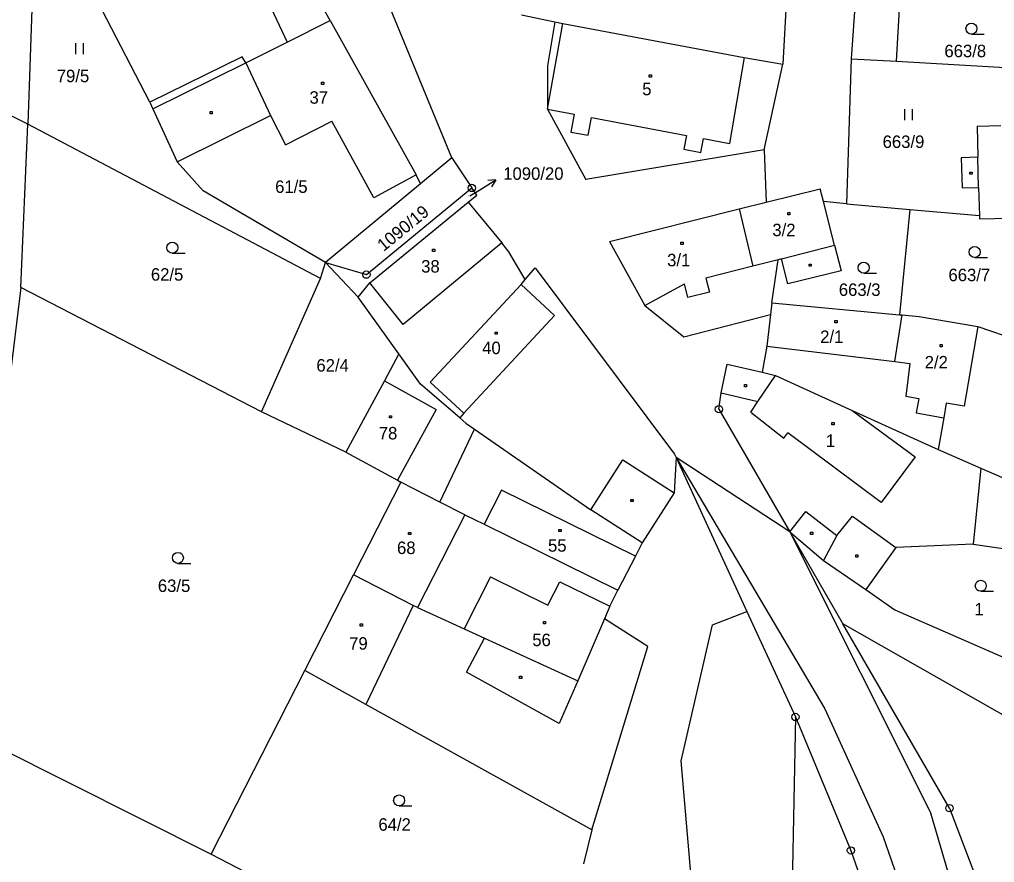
# Model space of a CAD drawing. Extents: x -794142 to -791199, y -1109267 to -1105626.
# Drawn here: x -793459.6 to -793326.7, y -1108046.6 to -1107931.8 of the extents above; entities that cross this region are included whole.
import ezdxf

# ---------------------------------------------------------------- set-up
doc = ezdxf.new("R2010")
doc.units = 0
for name, color, linetype in [('Komunikace', 7, 'Continuous'), ('Vrstva 1', 7, 'Continuous'), ('Vrstva 14', 7, 'Continuous'), ('Vrstva 15', 7, 'Continuous'), ('Vrstva 16', 7, 'Continuous'), ('Vrstva 2', 7, 'Continuous'), ('Vrstva 23', 7, 'Continuous'), ('Vrstva 25', 7, 'Continuous'), ('Vrstva 28', 7, 'Continuous')]:
    doc.layers.add(name, color=color, linetype=linetype)

msp = doc.modelspace()

# ---------------------------------------------------------------- linework, layer by layer
at = {"layer": 'Komunikace'}
msp.add_line((-793398.22, -1107955.82), (-793397.22, -1107955.2), dxfattribs=at)
at = {"layer": 'Vrstva 1'}
for p, q in [((-793354.79, -1107924.2), (-793355.57, -1107937.84)), ((-793345.34, -1107923.91), (-793346.26, -1107937.12)), ((-793400.69, -1107950.63), (-793411.16, -1107925.15)), ((-793425.68, -1107929.45), (-793423.1, -1107934.86)), ((-793417.25, -1107931.93), (-793418.43, -1107929.8)), ((-793457.93, -1107930.38), (-793458.47, -1107946.04)), ((-793441.86, -1107943.04), (-793448.32, -1107930.51)), ((-793391.17, -1107931.15), (-793386.63, -1107932.07)), ((-793340.09, -1107937.44), (-793339.66, -1107930.3)), ((-793423.1, -1107934.86), (-793417.25, -1107931.93)), ((-793386.63, -1107932.07), (-793387.62, -1107938.08)), ((-793386.63, -1107932.07), (-793385.56, -1107932.3)), ((-793385.56, -1107932.3), (-793360.83, -1107936.95)), ((-793428.76, -1107937.7), (-793423.1, -1107934.86)), ((-793429.25, -1107936.86), (-793441.86, -1107943.04)), ((-793428.76, -1107937.7), (-793429.25, -1107936.86)), ((-793387.62, -1107938.08), (-793387.63, -1107944.01)), ((-793360.83, -1107936.95), (-793355.57, -1107937.84)), ((-793358.12, -1107949.53), (-793355.57, -1107937.84)), ((-793346.26, -1107937.12), (-793346.9, -1107956.91)), ((-793346.26, -1107937.12), (-793340.09, -1107937.44)), ((-793340.09, -1107937.44), (-793319.65, -1107938.63)), ((-793441.86, -1107943.04), (-793441.44, -1107943.95)), ((-793458.47, -1107946.04), (-793462.94, -1107943.85)), ((-793441.44, -1107943.95), (-793438.11, -1107951.18)), ((-793387.63, -1107944.01), (-793382.42, -1107953.57)), ((-793459.42, -1107968.29), (-793458.47, -1107946.04)), ((-793418.59, -1107967.07), (-793458.47, -1107946.04)), ((-793438.11, -1107951.18), (-793425.38, -1107944.85)), ((-793425.38, -1107944.85), (-793423.36, -1107948.85)), ((-793423.36, -1107948.85), (-793417.03, -1107945.64)), ((-793411.32, -1107956.08), (-793417.03, -1107945.64)), ((-793329.08, -1107946.32), (-793325.86, -1107946.24)), ((-793329.08, -1107946.32), (-793328.97, -1107950.55)), ((-793358.12, -1107949.53), (-793382.42, -1107953.57)), ((-793358.12, -1107949.53), (-793357.84, -1107956.68)), ((-793434.57, -1107955.12), (-793438.11, -1107951.18)), ((-793400.69, -1107950.63), (-793404.94, -1107954.16)), ((-793400.69, -1107950.63), (-793397.96, -1107954.73)), ((-793328.97, -1107950.55), (-793331.25, -1107950.61)), ((-793331.25, -1107950.61), (-793331.14, -1107954.71)), ((-793405.56, -1107952.95), (-793411.32, -1107956.08)), ((-793404.94, -1107954.16), (-793405.56, -1107952.95)), ((-793417.88, -1107964.9), (-793434.57, -1107955.12)), ((-793404.94, -1107954.16), (-793417.88, -1107964.9)), ((-793412.32, -1107966.54), (-793397.96, -1107954.73)), ((-793397.26, -1107955.72), (-793397.96, -1107954.73)), ((-793357.84, -1107956.68), (-793350.49, -1107954.84)), ((-793350.04, -1107956.58), (-793350.49, -1107954.84)), ((-793331.14, -1107954.71), (-793328.87, -1107954.65)), ((-793328.87, -1107954.65), (-793328.77, -1107958.48)), ((-793411.84, -1107967.64), (-793398.46, -1107956.67)), ((-793398.46, -1107956.67), (-793397.26, -1107955.72)), ((-793398.46, -1107956.67), (-793393.84, -1107962.21)), ((-793361.5, -1107957.59), (-793357.84, -1107956.68)), ((-793348.52, -1107962.52), (-793350.04, -1107956.58)), ((-793346.9, -1107956.91), (-793350.04, -1107956.58)), ((-793379.19, -1107962.01), (-793361.5, -1107957.59)), ((-793361.5, -1107957.59), (-793359.65, -1107965.38)), ((-793346.9, -1107956.91), (-793338.24, -1107957.66)), ((-793338.24, -1107957.66), (-793339.66, -1107972)), ((-793338.24, -1107957.66), (-793328.77, -1107958.48)), ((-793328.77, -1107958.48), (-793328.76, -1107958.95)), ((-793328.76, -1107958.95), (-793324.56, -1107958.84)), ((-793379.19, -1107962.01), (-793374.36, -1107970.74)), ((-793392.89, -1107963.44), (-793393.84, -1107962.21)), ((-793348.52, -1107962.52), (-793347.61, -1107966.04)), ((-793390.68, -1107967.22), (-793392.89, -1107963.44)), ((-793356.22, -1107964.5), (-793359.65, -1107965.38)), ((-793357.08, -1107970.39), (-793356.22, -1107964.5)), ((-793355.76, -1107964.38), (-793356.22, -1107964.5)), ((-793354.89, -1107967.79), (-793355.76, -1107964.38)), ((-793418.59, -1107967.07), (-793417.88, -1107964.9)), ((-793417.88, -1107964.9), (-793413.45, -1107969.6)), ((-793417.88, -1107964.9), (-793412.32, -1107966.54)), ((-793390.68, -1107967.22), (-793389.34, -1107965.63)), ((-793389.34, -1107965.63), (-793370.31, -1107991)), ((-793426.6, -1107985.22), (-793418.59, -1107967.07)), ((-793391.24, -1107967.88), (-793390.68, -1107967.22)), ((-793347.61, -1107966.04), (-793354.89, -1107967.79)), ((-793459.42, -1107968.29), (-793461.03, -1107981.37)), ((-793426.6, -1107985.22), (-793459.42, -1107968.29)), ((-793413.45, -1107969.6), (-793411.84, -1107967.64)), ((-793391.24, -1107967.88), (-793403.64, -1107981.19)), ((-793407.88, -1107977.35), (-793413.45, -1107969.6)), ((-793374.36, -1107970.74), (-793369.06, -1107975.03)), ((-793357.08, -1107970.39), (-793357.26, -1107971.97)), ((-793357.08, -1107970.39), (-793339.66, -1107972)), ((-793369.06, -1107975.03), (-793357.26, -1107971.97)), ((-793357.26, -1107971.97), (-793357.74, -1107976.28)), ((-793340.28, -1107978.38), (-793339.3, -1107972.03)), ((-793339.66, -1107972), (-793339.3, -1107972.03)), ((-793339.3, -1107972.03), (-793337, -1107972.24)), ((-793337, -1107972.24), (-793329, -1107973.61)), ((-793329, -1107973.61), (-793330.86, -1107984.47)), ((-793329, -1107973.61), (-793319.59, -1107976.8)), ((-793357.74, -1107976.28), (-793358.38, -1107979.83)), ((-793407.88, -1107977.35), (-793409.86, -1107981.01)), ((-793404.93, -1107981.45), (-793407.88, -1107977.35)), ((-793363.98, -1107982.63), (-793363.16, -1107978.72)), ((-793363.16, -1107978.72), (-793358.38, -1107979.83)), ((-793340.28, -1107978.38), (-793338.27, -1107978.63)), ((-793338.27, -1107978.63), (-793338.81, -1107983.11)), ((-793358.38, -1107979.83), (-793356.55, -1107980.26)), ((-793356.55, -1107980.26), (-793346.11, -1107985.04)), ((-793409.86, -1107981.01), (-793415.13, -1107990.73)), ((-793399.6, -1107986.06), (-793404.93, -1107981.45)), ((-793403.64, -1107981.19), (-793399.04, -1107985.4)), ((-793364.27, -1107984.88), (-793363.98, -1107982.63)), ((-793338.81, -1107983.11), (-793337.03, -1107983.41)), ((-793337.03, -1107983.41), (-793337.37, -1107985.39)), ((-793333.28, -1107984.06), (-793333.62, -1107986.03)), ((-793330.86, -1107984.47), (-793333.28, -1107984.06)), ((-793415.13, -1107990.73), (-793426.6, -1107985.22)), ((-793399.04, -1107985.4), (-793399.6, -1107986.06)), ((-793364.27, -1107984.88), (-793354.61, -1108001.6)), ((-793346.11, -1107985.04), (-793336.22, -1107989.57)), ((-793337.37, -1107985.39), (-793333.62, -1107986.03)), ((-793398.77, -1107986.78), (-793399.6, -1107986.06)), ((-793398.77, -1107986.78), (-793397.58, -1107987.6)), ((-793333.62, -1107986.03), (-793334.37, -1107990.38)), ((-793402.31, -1107997.52), (-793397.58, -1107987.6)), ((-793397.58, -1107987.6), (-793381.71, -1107998.6)), ((-793336.22, -1107989.57), (-793334.37, -1107990.38)), ((-793415.13, -1107990.73), (-793408.06, -1107994.56)), ((-793370.31, -1107991), (-793370.11, -1107991.44)), ((-793334.37, -1107990.38), (-793328.57, -1107992.9)), ((-793370.11, -1107991.44), (-793370.36, -1107996.25)), ((-793370.11, -1107991.44), (-793360.47, -1108012.45)), ((-793354.61, -1108001.6), (-793370.11, -1107991.44)), ((-793328.57, -1107992.9), (-793319.74, -1107996.75)), ((-793407.62, -1107994.8), (-793414.08, -1108007.44)), ((-793408.06, -1107994.56), (-793407.62, -1107994.8)), ((-793402.31, -1107997.52), (-793407.62, -1107994.8)), ((-793370.36, -1107996.25), (-793374.72, -1108003.07)), ((-793398.9, -1107999.26), (-793402.31, -1107997.52)), ((-793374.72, -1108003.07), (-793381.71, -1107998.6)), ((-793398.9, -1107999.26), (-793405.36, -1108011.9)), ((-793398.9, -1107999.26), (-793396.25, -1108000.56)), ((-793396.25, -1108000.56), (-793378.03, -1108009.54)), ((-793354.61, -1108001.6), (-793347.39, -1108014.1)), ((-793354.61, -1108001.6), (-793350.03, -1108005.48)), ((-793374.72, -1108003.07), (-793375.65, -1108004.89)), ((-793340.14, -1108003.73), (-793344.24, -1108009.46)), ((-793329.63, -1108003.28), (-793340.14, -1108003.73)), ((-793329.63, -1108003.28), (-793320.7, -1108004.53)), ((-793375.65, -1108004.89), (-793378.03, -1108009.54)), ((-793350.03, -1108005.48), (-793344.24, -1108009.46)), ((-793420.73, -1108020.46), (-793414.08, -1108007.44)), ((-793405.94, -1108011.61), (-793414.08, -1108007.44)), ((-793379.14, -1108011.71), (-793378.03, -1108009.54)), ((-793344.24, -1108009.46), (-793340.28, -1108012.21)), ((-793405.36, -1108011.9), (-793405.94, -1108011.61)), ((-793405.36, -1108011.9), (-793399.01, -1108014.8)), ((-793379.14, -1108011.71), (-793379.88, -1108013.43)), ((-793365.13, -1108014.24), (-793360.47, -1108012.45)), ((-793360.47, -1108012.45), (-793353.85, -1108026.81)), ((-793340.28, -1108012.21), (-793322.91, -1108019.8)), ((-793379.88, -1108013.43), (-793383.52, -1108021.88)), ((-793373.96, -1108017.22), (-793379.88, -1108013.43)), ((-793399.01, -1108014.8), (-793396.22, -1108016.07)), ((-793369.41, -1108032.77), (-793365.13, -1108014.24)), ((-793310.44, -1108035.15), (-793347.39, -1108014.1)), ((-793332.85, -1108039.24), (-793347.39, -1108014.1)), ((-793396.22, -1108016.07), (-793383.52, -1108021.88)), ((-793381.6, -1108042.21), (-793373.96, -1108017.22)), ((-793433.49, -1108045.51), (-793420.73, -1108020.46)), ((-793412.4, -1108025.09), (-793420.73, -1108020.46)), ((-793381.6, -1108042.21), (-793412.4, -1108025.09)), ((-793353.85, -1108026.81), (-793355.86, -1108131.03)), ((-793353.85, -1108026.81), (-793346.28, -1108044.99)), ((-793466.87, -1108028.77), (-793433.49, -1108045.51)), ((-793367.78, -1108051.9), (-793369.41, -1108032.77)), ((-793332.85, -1108039.24), (-793329.45, -1108048.2)), ((-793381.6, -1108042.21), (-793382.75, -1108046.82)), ((-793433.49, -1108045.51), (-793412.17, -1108056.49)), ((-793346.28, -1108044.99), (-793340.14, -1108062.75))]:
    msp.add_line(p, q, dxfattribs=at)
at = {"layer": 'Vrstva 16'}
for p, q in [((-793397.22, -1107955.2), (-793394.669, -1107953.619)), ((-793394.669, -1107953.619), (-793395.783, -1107953.721)), ((-793394.669, -1107953.619), (-793395.256, -1107954.571))]:
    msp.add_line(p, q, dxfattribs=at)
at = {"layer": 'Vrstva 2'}
for p, q in [((-793417.25, -1107931.93), (-793405.56, -1107952.95)), ((-793387.63, -1107944.01), (-793385.56, -1107932.3)), ((-793441.44, -1107943.95), (-793428.76, -1107937.7)), ((-793428.76, -1107937.7), (-793425.38, -1107944.85)), ((-793360.83, -1107936.95), (-793362.84, -1107948.66)), ((-793387.63, -1107944.01), (-793384, -1107944.69)), ((-793384, -1107944.69), (-793384.45, -1107947.11)), ((-793382.11, -1107947.55), (-793381.66, -1107945.13)), ((-793381.66, -1107945.13), (-793368.71, -1107947.56)), ((-793384.45, -1107947.11), (-793382.11, -1107947.55)), ((-793368.71, -1107947.56), (-793369.07, -1107949.46)), ((-793366.72, -1107949.9), (-793366.37, -1107948)), ((-793366.37, -1107948), (-793362.84, -1107948.66)), ((-793369.07, -1107949.46), (-793366.72, -1107949.9)), ((-793328.87, -1107954.65), (-793328.97, -1107950.55)), ((-793393.84, -1107962.21), (-793407.3, -1107973.34)), ((-793355.76, -1107964.38), (-793348.52, -1107962.52)), ((-793359.65, -1107965.38), (-793366.04, -1107967.03)), ((-793366.04, -1107967.03), (-793365.56, -1107968.92)), ((-793407.3, -1107973.34), (-793411.84, -1107967.64)), ((-793386.67, -1107972.11), (-793391.24, -1107967.88)), ((-793374.36, -1107970.74), (-793368.98, -1107967.78)), ((-793368.5, -1107969.65), (-793368.98, -1107967.78)), ((-793365.56, -1107968.92), (-793368.5, -1107969.65)), ((-793386.67, -1107972.11), (-793399.04, -1107985.4)), ((-793357.74, -1107976.28), (-793340.28, -1107978.38)), ((-793358.96, -1107983.83), (-793356.55, -1107980.26)), ((-793409.86, -1107981.01), (-793402.81, -1107984.9)), ((-793363.98, -1107982.63), (-793358.96, -1107983.83)), ((-793359.91, -1107985.3), (-793358.96, -1107983.83)), ((-793402.81, -1107984.9), (-793408.06, -1107994.56)), ((-793359.91, -1107985.3), (-793355.43, -1107988.81)), ((-793346.11, -1107985.04), (-793337.54, -1107991.35)), ((-793355.43, -1107988.81), (-793354.89, -1107988.08)), ((-793342.15, -1107997.57), (-793354.89, -1107988.08)), ((-793381.71, -1107998.6), (-793377.35, -1107991.78)), ((-793377.35, -1107991.78), (-793370.36, -1107996.25)), ((-793370.11, -1107991.44), (-793349.84, -1108025.68)), ((-793337.54, -1107991.35), (-793342.15, -1107997.57)), ((-793328.57, -1107992.9), (-793329.63, -1108003.28)), ((-793393.92, -1107995.9), (-793396.25, -1108000.56)), ((-793375.65, -1108004.89), (-793393.92, -1107995.9)), ((-793354.61, -1108001.6), (-793352.42, -1107998.8)), ((-793352.42, -1107998.8), (-793348.22, -1108002.08)), ((-793348.22, -1108002.08), (-793346.07, -1107999.47)), ((-793346.07, -1107999.47), (-793340.14, -1108003.73)), ((-793354.61, -1108001.6), (-793335.41, -1108039.92)), ((-793348.22, -1108002.08), (-793350.03, -1108005.48)), ((-793395.39, -1108007.71), (-793399.01, -1108014.8)), ((-793395.39, -1108007.71), (-793387.57, -1108011.59)), ((-793387.57, -1108011.59), (-793385.95, -1108008.41)), ((-793385.95, -1108008.41), (-793379.14, -1108011.71)), ((-793405.94, -1108011.61), (-793412.4, -1108025.09)), ((-793398.67, -1108020.72), (-793396.22, -1108016.07)), ((-793386.05, -1108027.68), (-793398.67, -1108020.72)), ((-793383.52, -1108021.88), (-793386.05, -1108027.68)), ((-793349.84, -1108025.68), (-793341.9, -1108043.14)), ((-793329.37, -1108060.31), (-793335.41, -1108039.92)), ((-793341.9, -1108043.14), (-793335.73, -1108060.89))]:
    msp.add_line(p, q, dxfattribs=at)
at = {"layer": 'Vrstva 23'}
for p, q in [((-793329.85, -1107933.77), (-793328.1, -1107933.77)), ((-793451.92, -1107936.49), (-793451.92, -1107934.99)), ((-793450.92, -1107934.99), (-793450.92, -1107936.49)), ((-793338.93, -1107945.5), (-793338.93, -1107944)), ((-793337.93, -1107944), (-793337.93, -1107945.5)), ((-793438.78, -1107963.62), (-793437.03, -1107963.62)), ((-793329.41, -1107964.21), (-793327.66, -1107964.21)), ((-793344.54, -1107966.34), (-793342.79, -1107966.34)), ((-793438.01, -1108005.88), (-793436.26, -1108005.88)), ((-793328.58, -1108009.69), (-793326.83, -1108009.69)), ((-793407.86, -1108038.93), (-793406.11, -1108038.93))]:
    msp.add_line(p, q, dxfattribs=at)
for centre in [(-793329.85, -1107933.02), (-793438.78, -1107962.87), (-793329.41, -1107963.46), (-793344.54, -1107965.59), (-793438.01, -1108005.13), (-793328.58, -1108008.94), (-793407.86, -1108038.18)]:
    msp.add_circle(centre, 0.75, dxfattribs=at)
at = {"layer": 'Vrstva 25'}
for p, q in [((-793373.78, -1107939.33), (-793373.48, -1107939.33)), ((-793373.78, -1107939.63), (-793373.78, -1107939.33)), ((-793373.48, -1107939.33), (-793373.48, -1107939.63)), ((-793418.44, -1107940.32), (-793418.14, -1107940.32)), ((-793418.44, -1107940.62), (-793418.44, -1107940.32)), ((-793418.14, -1107940.62), (-793418.44, -1107940.62)), ((-793418.14, -1107940.32), (-793418.14, -1107940.62)), ((-793373.48, -1107939.63), (-793373.78, -1107939.63)), ((-793433.62, -1107944.32), (-793433.32, -1107944.32)), ((-793433.62, -1107944.62), (-793433.62, -1107944.32)), ((-793433.32, -1107944.62), (-793433.62, -1107944.62)), ((-793433.32, -1107944.32), (-793433.32, -1107944.62)), ((-793330.06, -1107952.56), (-793329.76, -1107952.56)), ((-793330.06, -1107952.86), (-793330.06, -1107952.56)), ((-793329.76, -1107952.56), (-793329.76, -1107952.86)), ((-793329.76, -1107952.86), (-793330.06, -1107952.86)), ((-793354.9, -1107958.09), (-793354.6, -1107958.09)), ((-793354.9, -1107958.39), (-793354.9, -1107958.09)), ((-793354.6, -1107958.39), (-793354.9, -1107958.39)), ((-793354.6, -1107958.09), (-793354.6, -1107958.39)), ((-793403.29, -1107963.08), (-793402.99, -1107963.08)), ((-793403.29, -1107963.38), (-793403.29, -1107963.08)), ((-793402.99, -1107963.08), (-793402.99, -1107963.38)), ((-793369.46, -1107962.12), (-793369.16, -1107962.12)), ((-793369.46, -1107962.42), (-793369.46, -1107962.12)), ((-793369.16, -1107962.42), (-793369.46, -1107962.42)), ((-793369.16, -1107962.12), (-793369.16, -1107962.42)), ((-793402.99, -1107963.38), (-793403.29, -1107963.38)), ((-793351.98, -1107965.09), (-793351.68, -1107965.09)), ((-793351.98, -1107965.39), (-793351.98, -1107965.09)), ((-793351.68, -1107965.39), (-793351.98, -1107965.39)), ((-793351.68, -1107965.09), (-793351.68, -1107965.39)), ((-793348.46, -1107972.79), (-793348.16, -1107972.79)), ((-793348.46, -1107973.09), (-793348.46, -1107972.79)), ((-793348.16, -1107973.09), (-793348.46, -1107973.09)), ((-793348.16, -1107972.79), (-793348.16, -1107973.09)), ((-793394.79, -1107974.36), (-793394.49, -1107974.36)), ((-793394.79, -1107974.66), (-793394.79, -1107974.36)), ((-793394.49, -1107974.66), (-793394.79, -1107974.66)), ((-793394.49, -1107974.36), (-793394.49, -1107974.66)), ((-793334.13, -1107976.06), (-793333.83, -1107976.06)), ((-793334.13, -1107976.36), (-793334.13, -1107976.06)), ((-793333.83, -1107976.36), (-793334.13, -1107976.36)), ((-793333.83, -1107976.06), (-793333.83, -1107976.36)), ((-793360.8, -1107981.52), (-793360.5, -1107981.52)), ((-793360.8, -1107981.82), (-793360.8, -1107981.52)), ((-793360.5, -1107981.82), (-793360.8, -1107981.82)), ((-793360.5, -1107981.52), (-793360.5, -1107981.82)), ((-793409.18, -1107985.77), (-793408.88, -1107985.77)), ((-793409.18, -1107986.07), (-793409.18, -1107985.77)), ((-793408.88, -1107985.77), (-793408.88, -1107986.07)), ((-793408.88, -1107986.07), (-793409.18, -1107986.07)), ((-793348.86, -1107986.7), (-793348.56, -1107986.7)), ((-793348.86, -1107987), (-793348.86, -1107986.7)), ((-793348.56, -1107987), (-793348.86, -1107987)), ((-793348.56, -1107986.7), (-793348.56, -1107987)), ((-793376.26, -1107997.16), (-793375.96, -1107997.16)), ((-793376.26, -1107997.46), (-793376.26, -1107997.16)), ((-793375.96, -1107997.46), (-793376.26, -1107997.46)), ((-793375.96, -1107997.16), (-793375.96, -1107997.46)), ((-793406.58, -1108001.66), (-793406.28, -1108001.66)), ((-793406.58, -1108001.96), (-793406.58, -1108001.66)), ((-793406.28, -1108001.66), (-793406.28, -1108001.96)), ((-793386.07, -1108001.26), (-793385.77, -1108001.26)), ((-793386.07, -1108001.56), (-793386.07, -1108001.26)), ((-793385.77, -1108001.56), (-793386.07, -1108001.56)), ((-793385.77, -1108001.26), (-793385.77, -1108001.56)), ((-793351.78, -1108001.64), (-793351.48, -1108001.64)), ((-793351.78, -1108001.94), (-793351.78, -1108001.64)), ((-793351.48, -1108001.64), (-793351.48, -1108001.94)), ((-793406.28, -1108001.96), (-793406.58, -1108001.96)), ((-793351.48, -1108001.94), (-793351.78, -1108001.94)), ((-793345.62, -1108004.72), (-793345.32, -1108004.72)), ((-793345.62, -1108005.02), (-793345.62, -1108004.72)), ((-793345.32, -1108005.02), (-793345.62, -1108005.02)), ((-793345.32, -1108004.72), (-793345.32, -1108005.02)), ((-793388.2, -1108013.8), (-793387.9, -1108013.8)), ((-793388.2, -1108014.1), (-793388.2, -1108013.8)), ((-793387.9, -1108013.8), (-793387.9, -1108014.1)), ((-793413.15, -1108014.12), (-793412.85, -1108014.12)), ((-793413.15, -1108014.42), (-793413.15, -1108014.12)), ((-793412.85, -1108014.42), (-793413.15, -1108014.42)), ((-793412.85, -1108014.12), (-793412.85, -1108014.42)), ((-793387.9, -1108014.1), (-793388.2, -1108014.1)), ((-793391.45, -1108021.26), (-793391.15, -1108021.26)), ((-793391.45, -1108021.56), (-793391.45, -1108021.26)), ((-793391.15, -1108021.56), (-793391.45, -1108021.56)), ((-793391.15, -1108021.26), (-793391.15, -1108021.56))]:
    msp.add_line(p, q, dxfattribs=at)
at = {"layer": 'Vrstva 28'}
for centre, radius in [((-793397.96, -1107954.73), 0.5), ((-793397.96, -1107954.73), 0.01), ((-793412.32, -1107966.54), 0.5), ((-793412.32, -1107966.54), 0.01), ((-793364.27, -1107984.88), 0.5), ((-793364.27, -1107984.88), 0.01), ((-793353.85, -1108026.81), 0.5), ((-793353.85, -1108026.81), 0.01), ((-793332.85, -1108039.24), 0.5), ((-793332.85, -1108039.24), 0.01), ((-793346.28, -1108044.99), 0.5), ((-793346.28, -1108044.99), 0.01)]:
    msp.add_circle(centre, radius, dxfattribs=at)

# ---------------------------------------------------------------- texts
at = {"layer": 'Vrstva 14'}
for s, height, p in [('663/8', 1.7, (-793333.54, -1107936.91)), ('79/5', 1.7, (-793454.523, -1107940.32)), ('663/9', 1.7, (-793341.96, -1107949.28)), ('61/5', 1.7, (-793424.76, -1107955.4)), ('1090/20', 0.1, (-793398.499, -1107955.82)), ('62/5', 1.7, (-793441.696, -1107967.36)), ('663/7', 1.7, (-793332.987, -1107967.43)), ('663/3', 1.7, (-793347.93, -1107969.44)), ('62/4', 1.7, (-793419.136, -1107979.75)), ('63/5', 1.7, (-793440.746, -1108009.78)), ('1', 1.7, (-793329.44, -1108012.97)), ('64/2', 1.7, (-793410.686, -1108042.31))]:
    msp.add_text(s, height=height, dxfattribs=at).set_placement(p)
msp.add_text('1090/19', height=1.7, rotation=39.25278, dxfattribs=at).set_placement((-793409.981, -1107963.459))
at = {"layer": 'Vrstva 15'}
for s, p in [('5', (-793374.723, -1107942.1)), ('37', (-793420.073, -1107943.25)), ('3/2', (-793356.99, -1107961.3)), ('38', (-793404.857, -1107966.26)), ('3/1', (-793371.333, -1107965.4)), ('2/1', (-793350.473, -1107975.85)), ('40', (-793396.542, -1107977.37)), ('2/2', (-793336.23, -1107979.32)), ('78', (-793410.633, -1107988.99)), ('1', (-793349.7, -1107990.02)), ('68', (-793408.147, -1108004.61)), ('55', (-793387.569, -1108004.29)), ('79', (-793414.673, -1108017.64)), ('56', (-793389.713, -1108017.16))]:
    msp.add_text(s, height=1.7, dxfattribs=at).set_placement(p)
at = {"layer": 'Vrstva 16'}
msp.add_text('1090/20', height=1.7, dxfattribs=at).set_placement((-793393.67, -1107953.62))

doc.saveas('drawing.dxf')
